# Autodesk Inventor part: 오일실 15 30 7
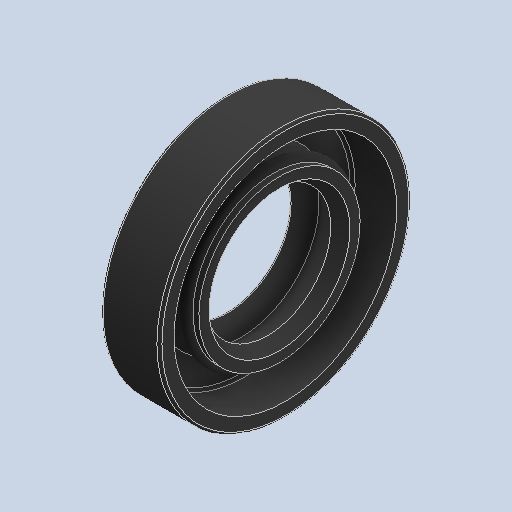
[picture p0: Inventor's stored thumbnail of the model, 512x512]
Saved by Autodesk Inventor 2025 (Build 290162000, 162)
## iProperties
Created: 2025-08
Part Number: 오일실 15 30 7
Material: 고무
Description: 오일-실
Document SubType Name: Modeling
Designer: infra028
Density: 0.93 g/cm^3
Appearance: 기본값
Author: jhkim
Sending System: Autodesk Inventor 2026
Preprocessor: ST-DEVELOPER v20.1
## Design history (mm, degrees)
feature "Solid1"
node "솔리드1"
